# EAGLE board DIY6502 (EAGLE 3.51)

Size 100 x 80 mm. Coordinates in mm from the lower left corner, seen from the top.
Outline: 0,0 100,0 100,80 0,80 0,0
Copper layers used: 

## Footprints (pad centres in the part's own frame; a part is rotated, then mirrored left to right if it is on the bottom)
-2,5 = drill 0.61 pad 1.27 octagon:  -1.27,0;  1.27,0
25M = drill 1.016 pad 1.575 octagon:  -16.764,1.397;  -13.97,1.397;  -11.176,1.397;  -8.382,1.397;  -5.588,1.397;  -2.794,1.397;  0,1.397;  2.794,1.397;  5.588,1.397;  8.382,1.397;  11.176,1.397;  13.97,1.397;  16.764,1.397;  -15.367,-1.397;  -12.573,-1.397;  -9.779,-1.397;  -6.985,-1.397;  -4.191,-1.397;  -1.397,-1.397;  1.397,-1.397;  4.191,-1.397;  6.985,-1.397;  9.779,-1.397;  12.573,-1.397;  15.367,-1.397 | hole 4.115: 23.368,0; -23.368,0
03 = drill 1.016 pad 1.575 octagon:  -2.54,0;  0,0;  2.54,0
22 = drill 1.016 pad 1.6 octagon:  -25.4,0;  -22.86,0;  -20.32,0;  -17.78,0;  -15.24,0;  -12.7,0;  -10.16,0;  -7.62,0;  -5.08,0;  -2.54,0;  0,0;  2.54,0;  5.08,0;  7.62,0;  10.16,0;  12.7,0;  15.24,0;  17.78,0;  20.32,0;  22.86,0;  25.4,0;  27.94,0
10 = drill 0.813 pad 1.397 octagon:  -5.08,0;  5.08,0
G-01 = drill 0.813 pad 1.397 octagon:  0,-3.81;  0,3.81
P-40 = drill 0.813 pad 1.397 square:  -1.27,7.62;  1.27,7.62;  3.81,7.62;  -3.81,7.62;  -6.35,7.62;  6.35,7.62;  -8.89,7.62;  8.89,7.62;  -11.43,7.62;  11.43,7.62;  13.97,7.62;  16.51,7.62;  -13.97,7.62;  -16.51,7.62;  19.05,7.62;  21.59,7.62;  24.13,7.62;  -19.05,7.62;  -21.59,7.62;  -24.13,7.62;  -1.27,-7.62;  -24.13,-7.62;  -21.59,-7.62;  -19.05,-7.62;  -16.51,-7.62;  -13.97,-7.62;  -11.43,-7.62;  -8.89,-7.62;  -6.35,-7.62;  -3.81,-7.62;  1.27,-7.62;  3.81,-7.62;  6.35,-7.62;  8.89,-7.62;  11.43,-7.62;  13.97,-7.62;  16.51,-7.62;  19.05,-7.62;  21.59,-7.62;  24.13,-7.62
L-14 = drill 0.813 pad 1.397 octagon:  -7.62,-3.81;  -5.08,-3.81;  7.62,-3.81;  7.62,3.81;  -2.54,-3.81;  0,-3.81;  5.08,-3.81;  2.54,-3.81;  5.08,3.81;  2.54,3.81;  0,3.81;  -2.54,3.81;  -5.08,3.81;  -7.62,3.81
L-16 = drill 0.813 pad 1.397 octagon:  -8.89,-3.81;  -6.35,-3.81;  6.35,-3.81;  8.89,-3.81;  -3.81,-3.81;  -1.27,-3.81;  3.81,-3.81;  1.27,-3.81;  8.89,3.81;  6.35,3.81;  3.81,3.81;  1.27,3.81;  -1.27,3.81;  -3.81,3.81;  -6.35,3.81;  -8.89,3.81
L24 = drill 0.813 pad 1.397 octagon:  -13.97,-7.62;  -11.43,-7.62;  1.27,-7.62;  3.81,-7.62;  -8.89,-7.62;  -6.35,-7.62;  -1.27,-7.62;  -3.81,-7.62;  6.35,-7.62;  8.89,-7.62;  11.43,-7.62;  13.97,-7.62;  13.97,7.62;  11.43,7.62;  8.89,7.62;  6.35,7.62;  3.81,7.62;  1.27,7.62;  -1.27,7.62;  -3.81,7.62;  -6.35,7.62;  -8.89,7.62;  -11.43,7.62;  -13.97,7.62
L-28 = drill 0.813 pad 1.397 octagon:  -16.51,-7.62;  -13.97,-7.62;  -1.27,-7.62;  1.27,-7.62;  -11.43,-7.62;  -8.89,-7.62;  -3.81,-7.62;  -6.35,-7.62;  3.81,-7.62;  6.35,-7.62;  8.89,-7.62;  11.43,-7.62;  13.97,-7.62;  16.51,-7.62;  16.51,7.62;  13.97,7.62;  11.43,7.62;  8.89,7.62;  6.35,7.62;  3.81,7.62;  1.27,7.62;  -1.27,7.62;  -3.81,7.62;  -6.35,7.62;  -8.89,7.62;  -11.43,7.62;  -13.97,7.62;  -16.51,7.62
P-28 = drill 0.813 pad 1.397 square:  6.35,7.62;  8.89,7.62;  11.43,7.62;  3.81,7.62;  1.27,7.62;  13.97,7.62;  -1.27,7.62;  16.51,7.62;  -3.81,7.62;  -6.35,7.62;  -8.89,7.62;  -11.43,7.62;  -13.97,7.62;  -16.51,7.62;  6.35,-7.62;  -16.51,-7.62;  -13.97,-7.62;  -11.43,-7.62;  -8.89,-7.62;  -6.35,-7.62;  -3.81,-7.62;  -1.27,-7.62;  1.27,-7.62;  3.81,-7.62;  8.89,-7.62;  11.43,-7.62;  13.97,-7.62;  16.51,-7.62
L20 = drill 0.813 pad 1.397 square:  0,0;  2.54,0;  5.08,0;  7.62,0;  10.16,0;  12.7,0;  15.24,0;  17.78,0;  20.32,0;  22.86,0;  22.86,7.62;  20.32,7.62;  17.78,7.62;  15.24,7.62;  12.7,7.62;  10.16,7.62;  7.62,7.62;  5.08,7.62;  2.54,7.62;  0,7.62
L14 = drill 0.813 pad 1.397 square:  0,0;  2.54,0;  5.08,0;  7.62,0;  10.16,0;  12.7,0;  15.24,0;  15.24,7.62;  12.7,7.62;  10.16,7.62;  7.62,7.62;  5.08,7.62;  2.54,7.62;  0,7.62
L14-4 = drill 0.813 pad 1.397 square:  -7.62,-3.81 | drill 0.813 pad 1.397 round:  7.62,-3.81;  7.62,3.81;  -7.62,3.81

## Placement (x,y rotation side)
C1  10æF  [-2,5]  11.9,9.52 0 top
J1  DB-25  [25M]  72.86,73.02 0 top
J2  2K/8K  [03]  91.91,15.87 0 top
J3  HDR22  [22]  4.28,38.73 270 top
R1  10Kê  [10]  28.41,8.25 90 top
R2  1Kê  [10]  22.06,8.25 90 top
S1  PUSH-BUTTON  [G-01]  10.63,4.44 90 top
U1  65C02  [P-40]  51.27,40 270 top
U2  7404  [L-14]  63.97,8.25 0 top
U3  74139  [L-16]  86.83,8.25 0 top
U4  6116  [L24]  70.32,33.65 270 top
U5  2864  [L-28]  89.37,37.46 270 top
U6  6551  [P-28]  33.49,43.81 270 top
U7  MAX233  [L20]  18.25,69.21 0 top
U8  6522  [P-40]  15.71,40 270 top
X1  1.000_MHz  [L14]  62.7,53.97 0 top
X2  1.8432_MHz  [L14-4]  42.38,8.25 180 top

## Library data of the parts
C1 R1 R2 = DISCRETE
J1 = CONNECT
J2 J3 = PINHEAD
S1 = SPECIAL
U1 U6 U8 = 65XXX
U2 U3 = 74XX
U4 = MYLIB0
U5 = MEMORY
U7 X1 X2 = OTHER

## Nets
8K: J2. U5.
A0: U1. U4. U5. U6. U8.
A1: U1. U4. U5. U6. U8.
A2: U1. U4. U5. U8.
A3: U1. U4. U5. U8.
A4: U1. U4. U5.
A5: U1. U4. U5.
A6: U1. U4. U5.
A7: U1. U4. U5.
A8: U1. U4. U5.
A9: U1. U4. U5.
A10: U1. U4. U5.
A11: J2. U1.
A12: U1. U2. U5. U6.
A13: U1. U3.
A14: U1. U3.
A15: U1. U2. U3. U4.
CA1: J3. U8.
CA2: J3. U8.
CB1: J3. U8.
CB2: J3. U8.
D0: U1. U4. U5. U6. U8.
D1: U1. U4. U5. U6. U8.
D2: U1. U4. U5. U6. U8.
D3: U1. U4. U5. U6. U8.
D4: U1. U4. U5. U6. U8.
D5: U1. U4. U5. U6. U8.
D6: U1. U4. U5. U6. U8.
D7: U1. U4. U5. U6. U8.
DSR: U6. U7.
DSR!: J1. U7.
DTR: U6. U7.
DTR!: J1. U7.
GND: U1. U2. U3. U4. U5. U6. U7. U8. X1. X2.
GNDA: C1. J1. R2. U1. U3.
IRQ: U1. U6.
N$1: R2. S1.
N$2: U6. X2.
N$3: U3. U4.
N$4: U3. U4.
N$5: U7.
N$6: U2. U8.
N$7: U7.
N$8: U7.
PA0: J3. U8.
PA1: J3. U8.
PA2: J3. U8.
PA3: J3. U8.
PA4: J3. U8.
PA5: J3. U8.
PA6: J3. U8.
PA7: J3. U8.
PB0: J3. U8.
PB1: J3. U8.
PB2: J3. U8.
PB3: J3. U8.
PB4: J3. U8.
PB5: J3. U8.
PB6: J3. U8.
PB7: J3. U8.
PHI2: U1. U6. U8.
PHI2-IN: U1. X1.
R/W: U1. U3. U6. U8.
RES*: C1. R1. S1. U1. U6. U8.
RXD: U6. U7.
RXD!: J1. U7.
TXD: U6. U7.
TXD!: J1. U7.
U2A!: U2. U3.
U3A-Y2: U3. U6. U8.
U3A-Y3: U3. U5.
VCC: J2. R1. U1. U2. U3. U4. U5. U6. U7. U8. X1. X2.

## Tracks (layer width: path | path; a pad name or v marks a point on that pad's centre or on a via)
8K  (1 unrouted)
A0  (4 unrouted)
A1  (4 unrouted)
A2  (3 unrouted)
A3  (3 unrouted)
A4  (2 unrouted)
A5  (2 unrouted)
A6  (2 unrouted)
A7  (2 unrouted)
A8  (2 unrouted)
A9  (2 unrouted)
A10  (2 unrouted)
A11  (1 unrouted)
A12  (3 unrouted)
A13  (1 unrouted)
A14  (1 unrouted)
A15  (3 unrouted)
CA1  (1 unrouted)
CA2  (1 unrouted)
CB1  (1 unrouted)
CB2  (1 unrouted)
D0  (4 unrouted)
D1  (4 unrouted)
D2  (4 unrouted)
D3  (4 unrouted)
D4  (4 unrouted)
D5  (4 unrouted)
D6  (4 unrouted)
D7  (4 unrouted)
DSR  (1 unrouted)
DSR!  (1 unrouted)
DTR  (1 unrouted)
DTR!  (1 unrouted)
GND  (10 unrouted)
GNDA  (4 unrouted)
IRQ  (1 unrouted)
N$1  (1 unrouted)
N$2  (1 unrouted)
N$3  (1 unrouted)
N$4  (1 unrouted)
N$5  (1 unrouted)
N$6  (1 unrouted)
N$7  (1 unrouted)
N$8  (1 unrouted)
PA0  (1 unrouted)
PA1  (1 unrouted)
PA2  (1 unrouted)
PA3  (1 unrouted)
PA4  (1 unrouted)
PA5  (1 unrouted)
PA6  (1 unrouted)
PA7  (1 unrouted)
PB0  (1 unrouted)
PB1  (1 unrouted)
PB2  (1 unrouted)
PB3  (1 unrouted)
PB4  (1 unrouted)
PB5  (1 unrouted)
PB6  (1 unrouted)
PB7  (1 unrouted)
PHI2  (2 unrouted)
PHI2-IN  (1 unrouted)
R/W  (3 unrouted)
RES*  (5 unrouted)
RXD  (1 unrouted)
RXD!  (1 unrouted)
TXD  (1 unrouted)
TXD!  (1 unrouted)
U2A!  (1 unrouted)
U3A-Y2  (2 unrouted)
U3A-Y3  (2 unrouted)
VCC  (12 unrouted)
